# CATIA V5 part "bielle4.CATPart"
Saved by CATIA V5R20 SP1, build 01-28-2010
Part number: bielle4
Bounding box of the stored display mesh (mm): x -105.824 to 3.176, y -5 to 5, z 138.093 to 151.907
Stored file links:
  E:\EDELI\gcausse\Edeli_2012_190_gcausse\bielle4.CATPart
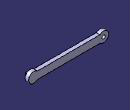
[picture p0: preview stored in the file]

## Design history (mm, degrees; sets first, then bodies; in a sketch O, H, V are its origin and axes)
Body1 (main body)
  Sketch1 on zx-plane, origin (0, 0, 0), H (-1, 0, 0), V (0, 0, 1)
    line L1 (93.9245, 150) -> (8.7225, 150)
    line L2 (93.9245, 140) -> (8.7225, 140)
    arc A1 centre (98.8235, 145) radius 7 from (93.9245, 150) to (93.9245, 140) cw
    point P5 (98.8235, 145)
    point P6 (103.7225, 140)
    arc A2 centre (3.8235, 145) radius 7 from (8.7225, 150) to (8.7225, 140) ccw
    point P7 (3.8235, 145)
    circle A3 centre (98.8235, 145) radius 2.5
    distance L1 L2 = 10
    radius A1 = 7
    radius A2 = 7
    distance P7 L1 = 5
    distance P5 L1 = 5
    distance P7 P5 = 95
    radius A3 = 2.5
    horizontal: L1 H, L2 H
    coincidence: A1 P6, P6 L2
  Pad1: profile Sketch1, direction (0, 1, 0), length 5
  Sketch2 on start face of Pad1, origin (0, 0, 0), H (1, 0, 0), V (0, 0, 1)
    circle A1 centre (-3.8235, 145) radius 1.5
    reference projected arc E1 centre (-3.8235, 145) radius 7 from (-8.7225, 140) to (-8.7225, 150) ccw from edge [start face of Pad1 | face of Pad1 from Sketch1.A2]
    reference projected arc E2 centre (-3.8235, 145) radius 7 from (-8.7225, 140) to (-8.7225, 150) ccw from edge [start face of Pad1 | face of Pad1 from Sketch1.A2]
    radius A1 = 1.5
    radius E1 = 7 (reference)
    concentricity: A1 E2
  Pad2: profile Sketch2, direction (0, -1, 0), length 5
